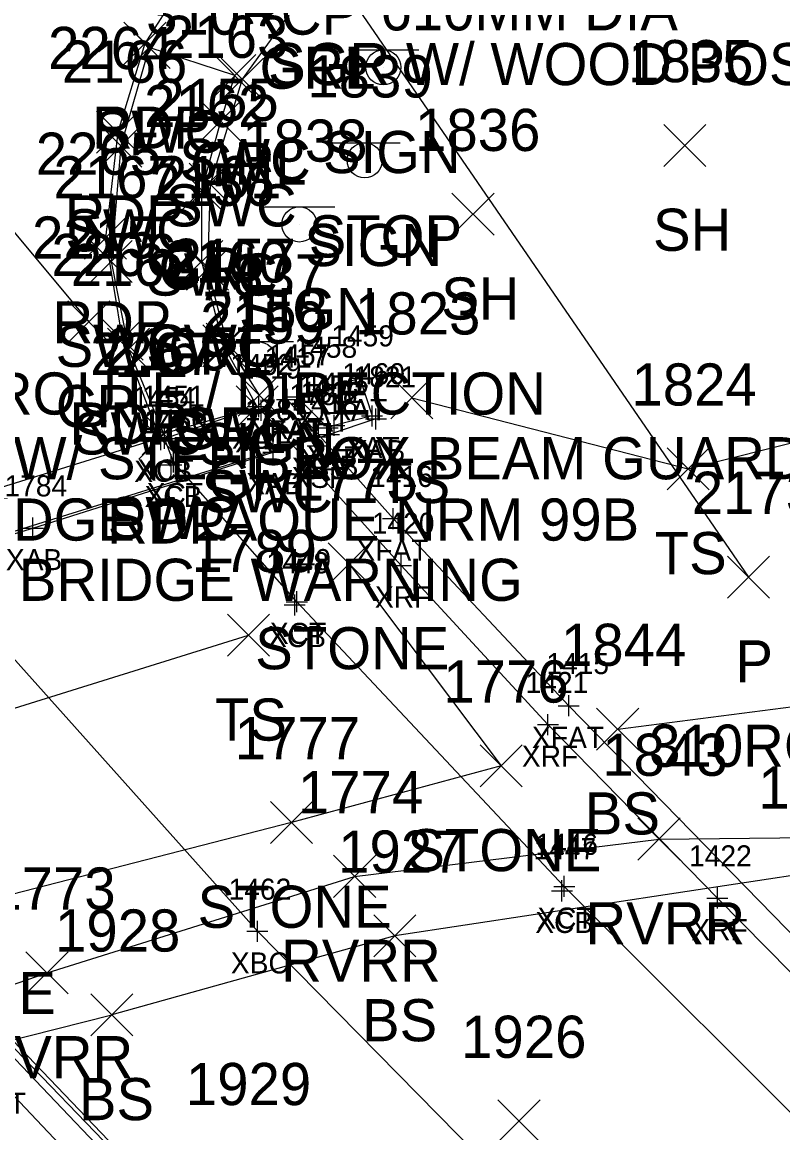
# Model space of a CAD drawing. Extents: x 1616726 to 1619875, y 273782 to 276557.
# Drawn here: x 1616959.7 to 1616995.8, y 276292.5 to 276345.2 of the extents above; entities that cross this region are included whole.
import ezdxf

# ---------------------------------------------------------------- set-up
doc = ezdxf.new("R2010")
doc.units = 0
for name, color, linetype in [('B_A', 7, 'Continuous'), ('B_C', 7, 'Continuous'), ('B_I', 7, 'Continuous'), ('B_TIC', 7, 'Continuous'), ('BDC', 7, 'Continuous'), ('BELB', 7, 'Continuous'), ('BF', 7, 'Continuous'), ('BR', 7, 'Continuous'), ('BSE', 7, 'Continuous'), ('BSUBM', 7, 'Continuous'), ('D_A', 7, 'Continuous'), ('D_C', 7, 'Continuous'), ('D_I', 7, 'Continuous'), ('D_TIC', 7, 'Continuous'), ('DCP', 7, 'Continuous'), ('L_A', 7, 'Continuous'), ('L_I', 7, 'Continuous'), ('L_TIC', 7, 'Continuous'), ('LASF', 7, 'Continuous'), ('LAWE', 7, 'Continuous'), ('LELB', 7, 'Continuous'), ('P_A', 7, 'Continuous'), ('P_I', 7, 'Continuous'), ('P_TIC', 7, 'Continuous'), ('PET', 7, 'Continuous'), ('PRC', 7, 'Continuous'), ('R_A', 7, 'Continuous'), ('R_C', 7, 'Continuous'), ('R_I', 7, 'Continuous'), ('R_TIC', 7, 'Continuous'), ('RGR', 7, 'Continuous'), ('RSW', 7, 'Continuous'), ('S_A', 7, 'Continuous'), ('S_C', 7, 'Continuous'), ('S_I', 7, 'Continuous'), ('SSGN', 7, 'Continuous'), ('U_C', 7, 'Continuous')]:
    doc.layers.add(name, color=color, linetype=linetype)

msp = doc.modelspace()

# ---------------------------------------------------------------- linework, layer by layer
at = {"layer": 'B_TIC'}
for p, q in [((1616975.73, 276328.281), (1616975.806, 276328.281)), ((1616973.984, 276327.743), (1616974.06, 276327.743)), ((1616972.29, 276327.269), (1616972.365, 276327.269)), ((1616972.753, 276327.383), (1616972.829, 276327.383)), ((1616970.941, 276326.925), (1616971.016, 276326.925)), ((1616971.058, 276326.754), (1616971.133, 276326.754)), ((1616976.319, 276326.485), (1616976.394, 276326.485)), ((1616976.5, 276326.338), (1616976.575, 276326.338)), ((1616974.215, 276325.913), (1616974.29, 276325.913)), ((1616974.28, 276325.603), (1616974.356, 276325.603)), ((1616974.519, 276326.035), (1616974.595, 276326.035)), ((1616966.296, 276325.356), (1616966.371, 276325.356)), ((1616966.461, 276325.419), (1616966.537, 276325.419)), ((1616973.737, 276325.067), (1616973.812, 276325.067)), ((1616973.77, 276325.498), (1616973.846, 276325.498)), ((1616971.628, 276324.769), (1616971.704, 276324.769)), ((1616966.781, 276324.16), (1616966.857, 276324.16)), ((1616966.901, 276324.299), (1616966.976, 276324.299)), ((1616977.321, 276321.612), (1616977.397, 276321.612)), ((1616960.218, 276321.164), (1616960.294, 276321.164)), ((1616977.696, 276319.392), (1616977.771, 276319.392)), ((1616972.747, 276317.666), (1616972.823, 276317.666)), ((1616972.645, 276317.513), (1616972.721, 276317.513)), ((1616985.655, 276312.733), (1616985.73, 276312.733)), ((1616984.67, 276311.834), (1616984.745, 276311.834)), ((1616985.443, 276304.157), (1616985.519, 276304.157)), ((1616985.328, 276303.949), (1616985.404, 276303.949)), ((1616992.712, 276303.608), (1616992.787, 276303.608)), ((1616970.879, 276302.028), (1616970.954, 276302.028))]:
    msp.add_line(p, q, dxfattribs=at)
for points in [[(1616975.727, 276327.781), (1616975.727, 276328.781)], [(1616973.981, 276327.243), (1616973.981, 276328.243)], [(1616975.227, 276328.281), (1616976.227, 276328.281)], [(1616972.286, 276326.769), (1616972.286, 276327.769)], [(1616972.75, 276326.883), (1616972.75, 276327.883)], [(1616973.481, 276327.743), (1616974.481, 276327.743)], [(1616970.937, 276326.425), (1616970.937, 276327.425)], [(1616971.054, 276326.254), (1616971.054, 276327.254)], [(1616971.786, 276327.269), (1616972.786, 276327.269)], [(1616972.25, 276327.383), (1616973.25, 276327.383)], [(1616970.437, 276326.925), (1616971.437, 276326.925)], [(1616970.554, 276326.754), (1616971.554, 276326.754)], [(1616976.315, 276325.985), (1616976.315, 276326.985)], [(1616976.496, 276325.838), (1616976.496, 276326.838)], [(1616974.211, 276325.413), (1616974.211, 276326.413)], [(1616974.277, 276325.103), (1616974.277, 276326.103)], [(1616974.516, 276325.535), (1616974.516, 276326.535)], [(1616975.815, 276326.485), (1616976.815, 276326.485)], [(1616975.996, 276326.338), (1616976.996, 276326.338)], [(1616966.292, 276324.856), (1616966.292, 276325.856)], [(1616966.458, 276324.919), (1616966.458, 276325.919)], [(1616973.711, 276325.913), (1616974.711, 276325.913)], [(1616973.733, 276324.567), (1616973.733, 276325.567)], [(1616973.767, 276324.998), (1616973.767, 276325.998)], [(1616973.777, 276325.603), (1616974.777, 276325.603)], [(1616974.016, 276326.035), (1616975.016, 276326.035)], [(1616965.792, 276325.356), (1616966.792, 276325.356)], [(1616965.958, 276325.419), (1616966.958, 276325.419)], [(1616971.625, 276324.269), (1616971.625, 276325.269)], [(1616973.233, 276325.067), (1616974.233, 276325.067)], [(1616973.267, 276325.498), (1616974.267, 276325.498)], [(1616966.778, 276323.66), (1616966.778, 276324.66)], [(1616966.897, 276323.799), (1616966.897, 276324.799)], [(1616971.125, 276324.769), (1616972.125, 276324.769)], [(1616966.278, 276324.16), (1616967.278, 276324.16)], [(1616966.397, 276324.299), (1616967.397, 276324.299)], [(1616977.318, 276321.112), (1616977.318, 276322.112)], [(1616960.215, 276320.664), (1616960.215, 276321.664)], [(1616976.818, 276321.612), (1616977.818, 276321.612)], [(1616959.715, 276321.164), (1616960.715, 276321.164)], [(1616977.692, 276318.892), (1616977.692, 276319.892)], [(1616977.192, 276319.392), (1616978.192, 276319.392)], [(1616972.244, 276317.666), (1616973.244, 276317.666)], [(1616972.642, 276317.013), (1616972.642, 276318.013)], [(1616972.744, 276317.166), (1616972.744, 276318.166)], [(1616972.142, 276317.513), (1616973.142, 276317.513)], [(1616985.651, 276312.233), (1616985.651, 276313.233)], [(1616985.151, 276312.733), (1616986.151, 276312.733)], [(1616984.666, 276311.334), (1616984.666, 276312.334)], [(1616984.166, 276311.834), (1616985.166, 276311.834)], [(1616985.44, 276303.657), (1616985.44, 276304.657)], [(1616984.94, 276304.157), (1616985.94, 276304.157)], [(1616985.325, 276303.449), (1616985.325, 276304.449)], [(1616992.708, 276303.108), (1616992.708, 276304.108)], [(1616984.825, 276303.949), (1616985.825, 276303.949)], [(1616992.208, 276303.608), (1616993.208, 276303.608)], [(1616970.875, 276301.528), (1616970.875, 276302.528)], [(1616970.375, 276302.028), (1616971.375, 276302.028)]]:
    msp.add_lwpolyline(points, dxfattribs=at)
at = {"layer": 'BDC'}
for points in [[(1617066.201, 276240.881), (1617061.118, 276239.32), (1617050.03, 276247.273), (1617037.28, 276257.235), (1617025.05, 276267.134), (1617011.056, 276279.412), (1616998.482, 276291.126), (1616985.44, 276304.157), (1616972.744, 276317.666), (1616966.897, 276324.299), (1616966.458, 276325.419), (1616970.937, 276326.925)], [(1617031.94, 276230.493), (1617019.04, 276240.812), (1617003.309, 276253.921), (1616987.272, 276268.372), (1616971.94, 276283.404), (1616957.293, 276298.592), (1616946.104, 276311.237), (1616940.906, 276317.316)], [(1617032.089, 276230.634), (1617019.011, 276240.957), (1617003.449, 276254.007), (1616987.219, 276268.519), (1616972.153, 276283.37), (1616957.519, 276298.646), (1616946.38, 276311.131), (1616940.99, 276317.433)]]:
    msp.add_lwpolyline(points, dxfattribs=at)
at = {"layer": 'BELB'}
msp.add_lwpolyline([(1616953.623, 276321.315), (1616970.875, 276302.028), (1616987.05, 276285.607), (1616997.927, 276275.138), (1617015.409, 276259.543), (1617031.053, 276246.557), (1617046.388, 276234.455)], dxfattribs=at)
at = {"layer": 'BF'}
for points in [[(1617068.317, 276241.506), (1617053.564, 276252.2), (1617041.697, 276261.369), (1617028.541, 276272.109), (1617018.019, 276281.339), (1617008.62, 276289.852), (1616999.219, 276298.836), (1616985.651, 276312.733), (1616977.318, 276321.612), (1616972.286, 276327.269)], [(1617030.013, 276230.064), (1617015.816, 276241.312), (1617001.537, 276253.314), (1616989.849, 276263.729), (1616982.397, 276270.726), (1616969.932, 276282.988), (1616958.21, 276295.373), (1616947.149, 276307.449), (1616939.121, 276316.789)]]:
    msp.add_lwpolyline(points, dxfattribs=at)
at = {"layer": 'BR'}
for points in [[(1616971.054, 276326.754), (1616977.692, 276319.392), (1616984.666, 276311.834), (1616992.708, 276303.608), (1616998.498, 276297.74), (1617007.24, 276289.498), (1617013.196, 276284.039), (1617021.735, 276276.403), (1617028.158, 276270.837), (1617038.653, 276262.201), (1617043.879, 276258.091), (1617053.125, 276251.01), (1617059.814, 276246.064), (1617066.819, 276241.017)], [(1616940.542, 276317.169), (1616949.786, 276306.506), (1616958.097, 276297.283), (1616966.707, 276288.28), (1616975.45, 276279.333), (1616984.398, 276270.583), (1616994.032, 276261.605), (1617003.798, 276253.031), (1617019.439, 276239.958), (1617030.784, 276230.919)]]:
    msp.add_lwpolyline(points, dxfattribs=at)
at = {"layer": 'BSE'}
msp.add_lwpolyline([(1616973.767, 276325.498), (1616940.561, 276315.184), (1616940.552, 276315.198)], dxfattribs=at)
at = {"layer": 'BSUBM'}
for points in [[(1616974.516, 276326.035), (1616974.211, 276325.913), (1616972.75, 276327.383), (1616973.981, 276327.743), (1616975.727, 276328.281), (1616976.315, 276326.485)], [(1616976.496, 276326.338), (1616974.277, 276325.603)], [(1616976.315, 276326.485), (1616974.516, 276326.035)], [(1616974.277, 276325.603), (1616971.625, 276324.769)], [(1616936.372, 276315.909), (1616937.33, 276313.997), (1616949.36, 276317.882), (1616960.215, 276321.164), (1616971.625, 276324.769)]]:
    msp.add_lwpolyline(points, dxfattribs=at)
at = {"layer": 'D_TIC'}
for points in [[(1616993.184, 276317.837), (1616995.184, 276319.837)], [(1616995.184, 276317.837), (1616993.184, 276319.837)]]:
    msp.add_lwpolyline(points, dxfattribs=at)
at = {"layer": 'DCP'}
msp.add_lwpolyline([(1616970.991, 276352.622), (1616994.184, 276318.837)], dxfattribs=at)
at = {"layer": 'L_TIC'}
for points in [[(1616990.161, 276338.318), (1616992.161, 276340.318)], [(1616992.161, 276338.318), (1616990.161, 276340.318)], [(1616980.105, 276335.055), (1616982.105, 276337.055)], [(1616982.105, 276335.055), (1616980.105, 276337.055)], [(1616977.199, 276326.348), (1616979.199, 276328.348)], [(1616979.199, 276326.348), (1616977.199, 276328.348)], [(1616990.321, 276322.975), (1616992.321, 276324.975)], [(1616992.321, 276322.975), (1616990.321, 276324.975)], [(1616974.225, 276318.463), (1616976.225, 276320.463)], [(1616976.225, 276318.463), (1616974.225, 276320.463)], [(1616969.447, 276315.077), (1616971.447, 276317.077)], [(1616971.447, 276315.077), (1616969.447, 276317.077)], [(1616986.975, 276310.623), (1616988.975, 276312.623)], [(1616988.975, 276310.623), (1616986.975, 276312.623)], [(1616981.445, 276308.881), (1616983.445, 276310.881)], [(1616983.445, 276308.881), (1616981.445, 276310.881)], [(1616971.489, 276306.194), (1616973.489, 276308.194)], [(1616973.489, 276306.194), (1616971.489, 276308.194)], [(1616988.935, 276305.407), (1616990.935, 276307.407)], [(1616990.935, 276305.407), (1616988.935, 276307.407)], [(1616974.487, 276303.634), (1616976.487, 276305.634)], [(1616976.487, 276303.634), (1616974.487, 276305.634)], [(1616976.398, 276300.812), (1616978.398, 276302.812)], [(1616978.398, 276300.812), (1616976.398, 276302.812)], [(1616959.888, 276299.059), (1616961.888, 276301.059)], [(1616961.888, 276299.059), (1616959.888, 276301.059)], [(1616962.959, 276297.067), (1616964.959, 276299.067)], [(1616964.959, 276297.067), (1616962.959, 276299.067)], [(1616982.29, 276292.025), (1616984.29, 276294.025)], [(1616984.29, 276292.025), (1616982.29, 276294.025)]]:
    msp.add_lwpolyline(points, dxfattribs=at)
at = {"layer": 'LASF'}
msp.add_lwpolyline([(1616975.225, 276319.463), (1616982.445, 276309.881), (1616972.489, 276307.194), (1616956.553, 276303.099), (1616948.662, 276305.969), (1616940.952, 276311.625)], dxfattribs=at)
at = {"layer": 'LAWE'}
msp.add_lwpolyline([(1616789.066, 276346.617), (1616813.729, 276340.234), (1616836.199, 276333.67), (1616856.332, 276327.47), (1616874.716, 276318.98), (1616895.397, 276309.259), (1616910.771, 276301.56), (1616920.919, 276300.828), (1616931.346, 276302.765), (1616941.571, 276299.741), (1616947.812, 276295.799), (1616953.389, 276297.474), (1616960.888, 276300.059), (1616975.487, 276304.634), (1616989.935, 276306.407), (1617005.692, 276306.569), (1617020.087, 276309.056), (1617036.575, 276315.223), (1617052.505, 276318.389), (1617064.656, 276321.245), (1617083.344, 276325.98), (1617106.129, 276330.762), (1617129.705, 276333.809)], dxfattribs=at)
at = {"layer": 'LELB'}
for points in [[(1616978.199, 276327.348), (1616991.321, 276323.975), (1617002.989, 276326.908), (1617009.955, 276326.56), (1617017.916, 276322.159), (1617029.869, 276324.32), (1617039.92, 276328.912), (1617046.634, 276333.892), (1617037.877, 276337.76), (1617028.239, 276334.405), (1617014.137, 276333.953), (1617001.116, 276333.136)], [(1617129.884, 276332.128), (1617121.079, 276329.53), (1617107.418, 276328.047), (1617085.495, 276323.643), (1617070.749, 276320.542), (1617052.825, 276314.228), (1617038.577, 276309.473), (1617032.524, 276309.943), (1617021.414, 276306.236), (1617009.943, 276306.043), (1616997.429, 276304.853), (1616977.398, 276301.812), (1616963.959, 276298.067)], [(1616987.975, 276311.623), (1617003.18, 276313.578), (1617018.055, 276316.199), (1617034.956, 276319.588)], [(1616951.715, 276310.243), (1616970.447, 276316.077)], [(1616948.067, 276294.055), (1616963.959, 276298.067)]]:
    msp.add_lwpolyline(points, dxfattribs=at)
at = {"layer": 'P_TIC'}
for points in [[(1616964.537, 276343.162), (1616966.537, 276345.162)], [(1616966.537, 276343.162), (1616964.537, 276345.162)], [(1616963.241, 276338.945), (1616965.241, 276340.945)], [(1616965.241, 276338.945), (1616963.241, 276340.945)], [(1616962.659, 276333.926), (1616964.659, 276335.926)], [(1616964.659, 276333.926), (1616962.659, 276335.926)], [(1616961.869, 276329.949), (1616963.869, 276331.949)], [(1616963.869, 276329.949), (1616961.869, 276331.949)], [(1616963.456, 276329.122), (1616965.456, 276331.122)], [(1616965.456, 276329.122), (1616963.456, 276331.122)], [(1616965.241, 276324.428), (1616967.241, 276326.428)], [(1616967.241, 276324.428), (1616965.241, 276326.428)]]:
    msp.add_lwpolyline(points, dxfattribs=at)
at = {"layer": 'PET'}
msp.add_lwpolyline([(1617014.404, 276374.536), (1616987.83, 276362.226), (1616976.678, 276357.843), (1616969.871, 276350.951), (1616965.537, 276344.162), (1616964.241, 276339.945), (1616963.659, 276334.926), (1616964.456, 276330.122), (1616966.241, 276325.428), (1616953.454, 276321.458), (1616940.91, 276317.633), (1616926.659, 276333.645), (1616912.071, 276350.842), (1616900.384, 276364.101), (1616887.78, 276376.027)], dxfattribs=at)
at = {"layer": 'PRC'}
msp.add_lwpolyline([(1616895.968, 276413.196), (1616909.569, 276395.506), (1616925.638, 276375.937), (1616938.47, 276360.406), (1616951.957, 276344.025), (1616962.869, 276330.949)], dxfattribs=at)
at = {"layer": 'R_TIC'}
for points in [[(1616964.735, 276342.971), (1616966.735, 276344.971)], [(1616966.735, 276342.971), (1616964.735, 276344.971)], [(1616968.801, 276341.629), (1616970.801, 276343.629)], [(1616970.801, 276341.629), (1616968.801, 276343.629)], [(1616969.155, 276341.461), (1616971.155, 276343.461)], [(1616971.155, 276341.461), (1616969.155, 276343.461)], [(1616968.132, 276339.474), (1616970.132, 276341.474)], [(1616970.132, 276339.474), (1616968.132, 276341.474)], [(1616963.393, 276338.292), (1616965.393, 276340.292)], [(1616965.393, 276338.292), (1616963.393, 276340.292)], [(1616967.626, 276336.48), (1616969.626, 276338.48)], [(1616969.626, 276336.48), (1616967.626, 276338.48)], [(1616967.236, 276336.193), (1616969.236, 276338.193)], [(1616969.236, 276336.193), (1616967.236, 276338.193)], [(1616962.932, 276332.811), (1616964.932, 276334.811)], [(1616964.932, 276332.811), (1616962.932, 276334.811)], [(1616967.23, 276332.812), (1616969.23, 276334.812)], [(1616969.23, 276332.812), (1616967.23, 276334.812)], [(1616967.502, 276332.447), (1616969.502, 276334.447)], [(1616969.502, 276332.447), (1616967.502, 276334.447)], [(1616968.439, 276328.892), (1616970.439, 276330.892)], [(1616970.439, 276328.892), (1616968.439, 276330.892)], [(1616963.754, 276328.653), (1616965.754, 276330.653)], [(1616965.754, 276328.653), (1616963.754, 276330.653)], [(1616968.286, 276328.813), (1616970.286, 276330.813)], [(1616970.286, 276328.813), (1616968.286, 276330.813)], [(1616969.958, 276326.471), (1616971.958, 276328.471)], [(1616971.958, 276326.471), (1616969.958, 276328.471)], [(1616969.859, 276325.911), (1616971.859, 276327.911)], [(1616971.859, 276325.911), (1616969.859, 276327.911)], [(1616965.408, 276324.644), (1616967.408, 276326.644)], [(1616967.408, 276324.644), (1616965.408, 276326.644)]]:
    msp.add_lwpolyline(points, dxfattribs=at)
at = {"layer": 'RGR'}
msp.add_lwpolyline([(1616987.556, 276351.179), (1616982.476, 276351.595), (1616977.549, 276350.197), (1616973.431, 276347.007), (1616970.155, 276342.461), (1616968.626, 276337.48), (1616968.502, 276333.447), (1616969.439, 276329.892), (1616970.958, 276327.471)], dxfattribs=at)
at = {"layer": 'RSW'}
for points in [[(1616970.859, 276326.911), (1616969.286, 276329.813), (1616968.23, 276333.812), (1616968.236, 276337.193), (1616969.132, 276340.474), (1616969.801, 276342.629), (1616965.735, 276343.971), (1616964.393, 276339.292), (1616963.932, 276333.811), (1616964.754, 276329.653), (1616966.408, 276325.644)], [(1616966.408, 276325.644), (1616970.859, 276326.911)]]:
    msp.add_lwpolyline(points, dxfattribs=at)
at = {"layer": 'SSGN'}
for p, q in [((1616975.201, 276343.858), (1616978.534, 276343.858)), ((1616976.847, 276343.025), (1616976.847, 276343.025)), ((1616974.318, 276339.446), (1616977.651, 276339.446)), ((1616975.965, 276338.613), (1616975.965, 276338.613)), ((1616971.214, 276336.401), (1616974.547, 276336.401)), ((1616972.861, 276335.568), (1616972.861, 276335.568)), ((1616969.256, 276330.008), (1616972.589, 276330.008)), ((1616970.903, 276329.175), (1616970.903, 276329.175))]:
    msp.add_line(p, q, dxfattribs=at)
for centre in [(1616976.847, 276343.025), (1616975.965, 276338.613), (1616972.861, 276335.568), (1616970.903, 276329.175)]:
    msp.add_circle(centre, 0.833, dxfattribs=at)

# ---------------------------------------------------------------- texts
at = {"layer": 'B_A'}
for s, p in [('XAT', (1616974.431, 276326.281)), ('XAT', (1616972.685, 276325.743)), ('XFAT', (1616970.542, 276325.269)), ('XAT', (1616971.455, 276325.383)), ('XCT', (1616969.658, 276324.925)), ('XRF', (1616969.814, 276324.754)), ('XAT', (1616973.22, 276324.035)), ('XAT', (1616975.02, 276324.485)), ('XAB', (1616975.217, 276324.338)), ('XBS', (1616972.507, 276323.498)), ('XAT', (1616972.916, 276323.913)), ('XAB', (1616972.997, 276323.603)), ('XCB', (1616965.029, 276323.356)), ('XCT', (1616965.178, 276323.419)), ('XSF', (1616972.493, 276323.067)), ('XAB', (1616970.345, 276322.769)), ('XCB', (1616965.514, 276322.16)), ('XCT', (1616965.618, 276322.299)), ('XFAT', (1616975.574, 276319.612)), ('XAB', (1616958.935, 276319.164)), ('XRF', (1616976.452, 276317.392)), ('XCT', (1616971.464, 276315.666)), ('XCB', (1616971.378, 276315.513)), ('XFAT', (1616983.907, 276310.733)), ('XRF', (1616983.426, 276309.834)), ('XCB', (1616984.061, 276301.949)), ('XCT', (1616984.16, 276302.157)), ('XRF', (1616991.468, 276301.608)), ('XBC', (1616969.612, 276300.028)), ('XFAT', (1616956.466, 276293.373))]:
    msp.add_text(s, height=1, dxfattribs=at).set_placement(p)
at = {"layer": 'B_C'}
for s, p in [('CONCRETE CURBING W/ STEEL BOX BEAM GUARDRAIL', (1616930.467, 276323.477)), ('BRIDGE PLAQUE NRM 99B', (1616954.812, 276320.567))]:
    msp.add_text(s, height=2, dxfattribs=at).set_placement(p)
at = {"layer": 'B_I'}
for s, p in [('1459', (1616974.376, 276329.781)), ('1457', (1616971.403, 276328.883)), ('1458', (1616972.634, 276329.243)), ('1452', (1616969.591, 276328.425)), ('1419', (1616969.987, 276328.254)), ('1417', (1616971.223, 276328.769)), ('1460', (1616974.902, 276327.985)), ('1821', (1616975.433, 276327.838)), ('1456', (1616972.837, 276327.413)), ('1455', (1616973.169, 276327.535)), ('1454', (1616964.946, 276326.856)), ('1451', (1616965.395, 276326.919)), ('1786', (1616972.393, 276326.998)), ('1822', (1616972.93, 276327.103)), ('1785', (1616970.278, 276326.269)), ('1418', (1616972.67, 276326.567)), ('1453', (1616965.431, 276325.66)), ('1450', (1616965.507, 276325.799)), ('1416', (1616976.227, 276323.112)), ('1784', (1616958.868, 276322.664)), ('1420', (1616976.303, 276320.892)), ('1448', (1616971.295, 276319.013)), ('1449', (1616971.393, 276319.166)), ('1415', (1616984.588, 276314.233)), ('1421', (1616983.603, 276313.334)), ('1446', (1616984.066, 276305.657)), ('1447', (1616983.978, 276305.449)), ('1422', (1616991.362, 276305.108)), ('1462', (1616969.505, 276303.528))]:
    msp.add_text(s, height=1, dxfattribs=at).set_placement(p)
at = {"layer": 'D_A'}
msp.add_text('P', height=2, dxfattribs=at).set_placement((1616993.561, 276313.837))
at = {"layer": 'D_C'}
for p in [(1616965.595, 276344.574), (1616989.467, 276309.837)]:
    msp.add_text('310RCP', height=2, dxfattribs=at).set_placement(p)
at = {"layer": 'D_I'}
msp.add_text('2173', height=2, dxfattribs=at).set_placement((1616991.491, 276321.837))
at = {"layer": 'L_A'}
for s, p in [('SH', (1616989.649, 276334.318)), ('SH', (1616979.593, 276331.055)), ('TS', (1616976.608, 276322.348)), ('TS', (1616989.73, 276318.975)), ('STONE', (1616970.768, 276314.463)), ('TS', (1616968.857, 276311.077)), ('BS', (1616986.416, 276306.623)), ('STONE', (1616977.988, 276304.881)), ('STONE', (1616968.033, 276302.194)), ('RVRR', (1616986.447, 276301.407)), ('RVRR', (1616971.999, 276299.634)), ('STONE', (1616952.096, 276298.099)), ('BS', (1616975.839, 276296.812)), ('RVRR', (1616957.4, 276295.059)), ('BS', (1616962.4, 276293.067))]:
    msp.add_text(s, height=2, dxfattribs=at).set_placement(p)
at = {"layer": 'L_I'}
for s, p in [('1835', (1616988.468, 276342.318)), ('1836', (1616978.356, 276339.055)), ('1823', (1616975.506, 276330.348)), ('1824', (1616988.628, 276326.975)), ('1775', (1616972.532, 276322.463)), ('1789', (1616967.747, 276319.077)), ('1844', (1616985.282, 276314.623)), ('1776', (1616979.697, 276312.881)), ('1777', (1616969.796, 276310.194)), ('1843', (1616987.242, 276309.407)), ('1920', (1616994.649, 276307.853)), ('1774', (1616972.795, 276307.634)), ('1927', (1616974.705, 276304.812)), ('1773', (1616958.195, 276303.059)), ('1928', (1616961.266, 276301.067)), ('1926', (1616980.542, 276296.025)), ('1929', (1616967.477, 276293.783))]:
    msp.add_text(s, height=2, dxfattribs=at).set_placement(p)
at = {"layer": 'P_A'}
for s, p in [('RDP', (1616963.026, 276339.162)), ('RDP', (1616961.73, 276334.945)), ('RDP', (1616961.147, 276329.926)), ('CR', (1616961.303, 276325.949)), ('RDP', (1616961.944, 276325.122)), ('RDP', (1616963.729, 276320.428))]:
    msp.add_text(s, height=2, dxfattribs=at).set_placement(p)
at = {"layer": 'P_I'}
for s, p in [('2264', (1616960.934, 276342.945)), ('2265', (1616960.352, 276337.926)), ('2215', (1616960.177, 276333.949)), ('2266', (1616961.094, 276333.122)), ('2267', (1616962.934, 276328.428))]:
    msp.add_text(s, height=2, dxfattribs=at).set_placement(p)
at = {"layer": 'R_A'}
for s, p in [('GRL', (1616970.975, 276342.007)), ('SWC', (1616963.097, 276338.971)), ('SWC', (1616967.164, 276337.629)), ('GRL', (1616967.698, 276337.461)), ('SWC', (1616966.494, 276335.474)), ('SWC', (1616961.755, 276334.292)), ('SWC', (1616965.598, 276332.193)), ('GRL', (1616966.169, 276332.48)), ('SWC', (1616961.295, 276328.811)), ('SWC', (1616965.592, 276328.812)), ('GRL', (1616966.046, 276328.447)), ('SWC', (1616962.116, 276324.653)), ('SWC', (1616966.648, 276324.813)), ('GRL', (1616966.983, 276324.892)), ('GRL', (1616968.501, 276322.471)), ('SWC', (1616968.221, 276321.911)), ('SWC', (1616963.77, 276320.644))]:
    msp.add_text(s, height=2, dxfattribs=at).set_placement(p)
at = {"layer": 'R_C'}
msp.add_text('SGR W/ WOOD POSTS', height=2, dxfattribs=at).set_placement((1616971.382, 276342.179))
at = {"layer": 'R_I'}
for s, p in [('2163', (1616966.392, 276343.474)), ('2166', (1616961.597, 276342.292)), ('2155', (1616965.933, 276340.48)), ('2162', (1616965.495, 276340.193)), ('2167', (1616961.192, 276336.811)), ('2161', (1616966.057, 276336.812)), ('2156', (1616965.754, 276336.447)), ('2168', (1616962.014, 276332.653)), ('2160', (1616966.459, 276332.813)), ('2157', (1616966.746, 276332.892)), ('2158', (1616968.265, 276330.471)), ('2159', (1616968.158, 276329.911)), ('2169', (1616963.66, 276328.644))]:
    msp.add_text(s, height=2, dxfattribs=at).set_placement(p)
at = {"layer": 'S_A'}
for p in [(1616973.985, 276338.005), (1616973.102, 276333.593), (1616969.999, 276330.547), (1616968.04, 276324.155)]:
    msp.add_text('SIGN', height=2, dxfattribs=at).set_placement(p)
at = {"layer": 'S_C'}
for s, p in [('STOP', (1616973.308, 276334.005)), ('ROUTE / DIRECTION', (1616958.267, 276326.547)), ('BRIDGE WARNING', (1616959.551, 276317.708))]:
    msp.add_text(s, height=2, dxfattribs=at).set_placement(p)
at = {"layer": 'S_I'}
for s, p in [('1839', (1616973.244, 276341.593)), ('1838', (1616970.148, 276338.547)), ('1837', (1616968.19, 276332.155))]:
    msp.add_text(s, height=2, dxfattribs=at).set_placement(p)
at = {"layer": 'U_C'}
msp.add_text('610MM DIA', height=2, dxfattribs=at).set_placement((1616976.712, 276344.776))

doc.saveas('drawing.dxf')
